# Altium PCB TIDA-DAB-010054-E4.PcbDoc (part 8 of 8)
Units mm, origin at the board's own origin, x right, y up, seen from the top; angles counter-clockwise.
Board outline 300 x 180 mm, 4 copper layers (Top Layer, Inner Layer1, Inner Layer2, Bottom Layer), stack 1.605 mm thick; 873 components, 388 nets, 2405 pads, 1542 vias.
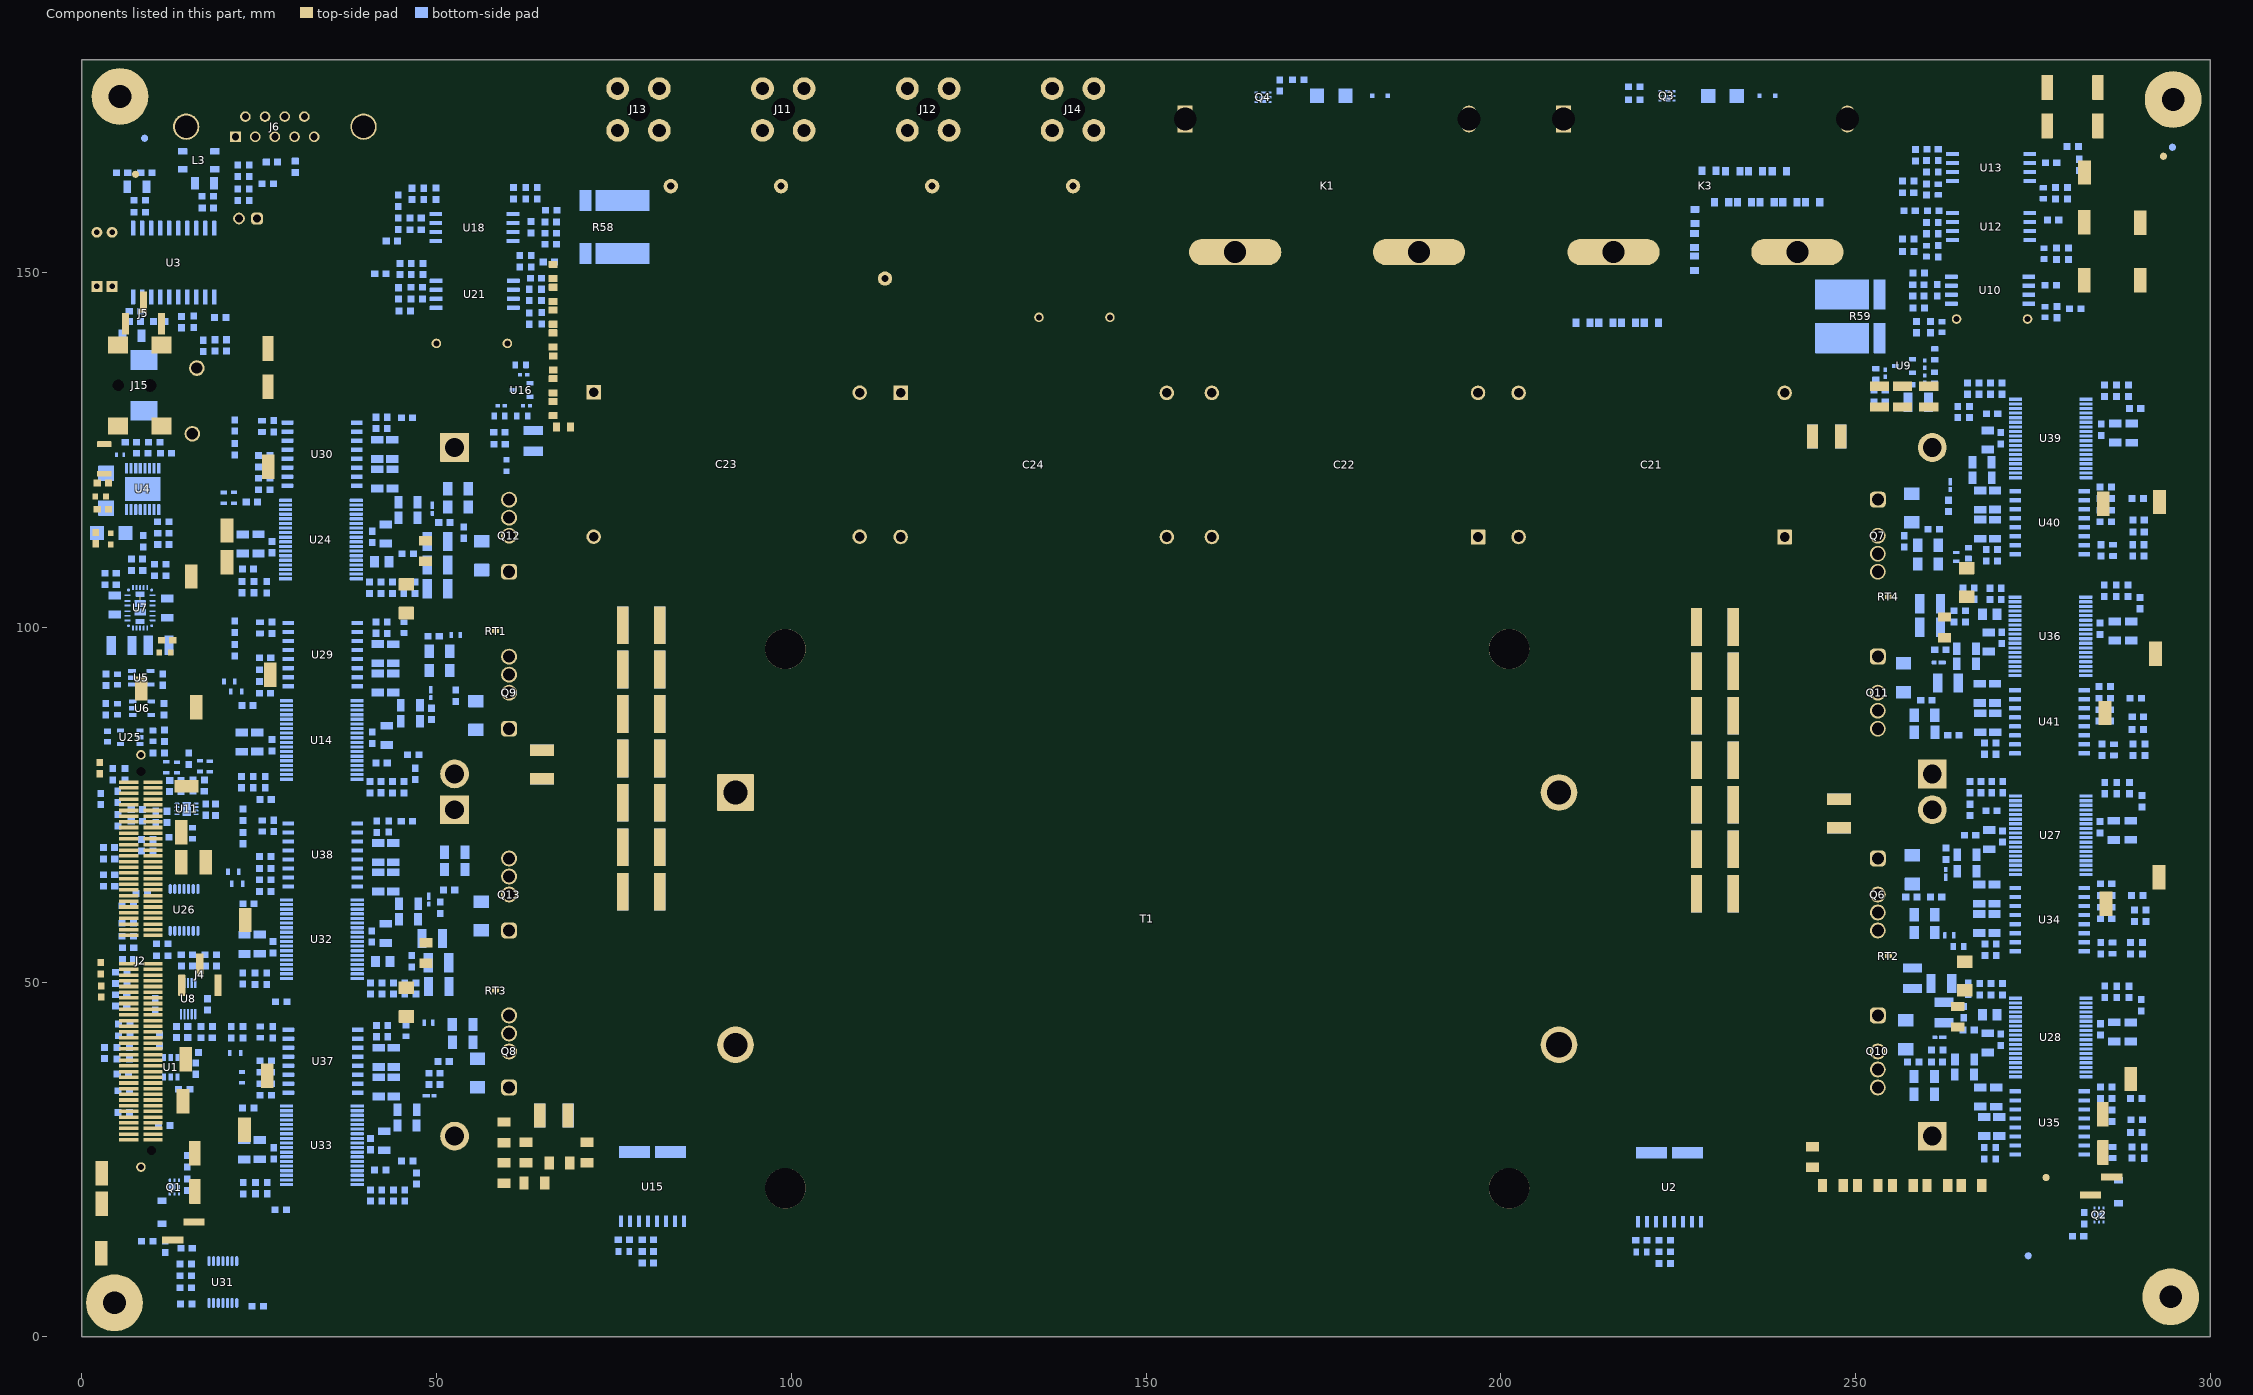
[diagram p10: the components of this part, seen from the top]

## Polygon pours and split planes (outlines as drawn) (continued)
-4V_BOT2 on Bottom Layer "BOTTOM_LAYER_-4V_BOT2_P194" (solid, remove dead copper, pour order 194): 42.729,54.117 42.61,53.998 40.244,53.998 39.815,53.569 37.904,53.569 37.904,54.664 42.729,54.664
+15V_BOT2 on Bottom Layer "BOTTOM_LAYER_+15V_BOT2_P193" (solid, remove dead copper, pour order 193): 37.92,55.769 37.904,55.753 37.904,54.857 46.897,54.857 46.897,57.232 44.868,57.232 43.563,55.927 39.89,55.927 39.745,55.782
-4V_BOT2 on Bottom Layer "BOTTOM_LAYER_-4V_BOT2_P192" (solid, remove dead copper, pour order 192): 39.852,63.799 40.108,63.543 45.372,63.543 45.372,57.916 44.478,57.916 42.956,56.394 39.945,56.394 39.549,55.999 39.534,56.014 37.924,56.014 37.924,63.799
S2L_P on Bottom Layer "BOTTOM_LAYER_S2L_P_P191" (solid, remove dead copper, pour order 191): 46.168,71.806 47.109,71.806 47.109,69.047 37.938,69.047 37.938,69.982 37.924,69.997 37.924,70.257 39.549,70.257 41.098,71.806
+15V_BOT2 on Bottom Layer "BOTTOM_LAYER_+15V_BOT2_P190" (solid, remove dead copper, pour order 190): 37.924,67.629 37.924,66.968 37.953,66.938 39.815,66.938 40.525,66.228 40.525,65.532 41.118,64.94 47.009,64.94 47.009,67.629 39.94,67.629 39.549,67.629
-4V_TOP1 on Bottom Layer "BOTTOM_LAYER_-4V_TOP1_P006" (solid, remove dead copper, pour order 6): 39.81,92.033 40.315,91.528 45.472,91.528 45.472,86.15 44.578,86.15 43.056,84.628 40.045,84.628 39.649,84.233 39.634,84.248 38.024,84.248 38.024,91.88 38.039,92.023 38.05,92.033
+15V_TOP1 on Bottom Layer "BOTTOM_LAYER_+15V_TOP1_P007" (solid, remove dead copper, pour order 7): 38.02,84.003 38.004,83.987 38.004,82.898 46.997,82.898 46.997,85.466 44.968,85.466 43.663,84.161 39.99,84.161 39.845,84.016
-4V_TOP1 on Bottom Layer "BOTTOM_LAYER_-4V_TOP1_P008" (solid, remove dead copper, pour order 8): 38.004,81.618 42.829,81.618 42.829,82.698 38.033,82.698 38.004,82.669
S1H_P on Bottom Layer "BOTTOM_LAYER_S1H_P_P175" (solid, remove dead copper, pour order 175): 44.998,79.015 44.217,79.015 42.958,80.274 42.564,80.274 42.564,81.34 44.998,81.34
S1L_P on Bottom Layer "BOTTOM_LAYER_S1L_P_P182" (solid, remove dead copper, pour order 182): 37.92,125.832 47.596,125.832 47.596,128.515 41.319,128.515 39.549,126.745 37.92,126.745
+15V_TOP1 on Bottom Layer "BOTTOM_LAYER_+15V_TOP1_P004" (solid, remove dead copper, pour order 4): 38.024,95.862 38.024,95.202 38.053,95.172 39.915,95.172 40.625,94.462 40.625,92.89 47.109,92.89 47.109,95.862 40.04,95.862 39.649,95.862
S1H_P on Bottom Layer "BOTTOM_LAYER_S1H_P_P005" (solid, remove dead copper, pour order 5): 40.416,97.507 40.869,97.054 40.869,97.048 47.352,97.048 47.352,97.509 47.35,97.511 47.35,98.461 46.03,99.78 40.939,99.78 39.649,98.491 38.024,98.491 38.024,98.23 38.038,98.216 38.038,97.507
-4V_TOP1 on Bottom Layer "BOTTOM_LAYER_-4V_TOP1_P176" (solid, remove dead copper, pour order 176): 46.356,77.031 40.143,77.031 39.709,77.465 39.709,79.433 38.053,79.433 38.03,79.411 38.059,79.382 38.059,76.224 46.356,76.224
+15V_BOT1 on Bottom Layer "BOTTOM_LAYER_+15V_BOT1_P181" (solid, remove dead copper, pour order 181): 37.923,124.117 37.923,123.456 37.953,123.427 39.815,123.427 40.525,122.716 40.525,121.678 46.773,121.678 46.773,124.296 40.119,124.296 39.94,124.117 39.549,124.117
-4V_BOT1 on Bottom Layer "BOTTOM_LAYER_-4V_BOT1_P183" (solid, remove dead copper, pour order 183): 37.939,120.277 37.949,120.287 40.288,120.287 45.372,120.287 45.372,114.404 44.478,114.404 42.956,112.882 39.944,112.882 39.549,112.487 39.534,112.502 37.923,112.502 37.923,120.135
+15V_BOT1 on Bottom Layer "BOTTOM_LAYER_+15V_BOT1_P184" (solid, remove dead copper, pour order 184): 37.92,112.257 37.904,112.241 37.904,111.152 46.897,111.152 46.897,113.72 44.867,113.72 43.562,112.415 39.889,112.415 39.744,112.27
-4V_BOT1 on Bottom Layer "BOTTOM_LAYER_-4V_BOT1_P185" (solid, remove dead copper, pour order 185): 43.149,110.256 40.052,110.256 39.649,109.854 39.631,109.872 37.904,109.872 37.904,110.923 37.932,110.952 43.149,110.952
-4V_BOT1 on Bottom Layer "BOTTOM_LAYER_-4V_BOT1_P186" (solid, remove dead copper, pour order 186): 46.255,105.285 40.043,105.285 39.608,105.719 39.608,107.688 37.952,107.688 37.93,107.665 37.958,107.636 37.958,104.207 46.255,104.207
I_SEC_P on Bottom Layer "BOTTOM_LAYER_I_SEC_P_P168" (solid, remove dead copper, pour order 168): 218.51,24.8 218.51,29.163 218.497,29.163 215.02,32.64 203.84,32.64 202.76,33.72 202.76,48.58 203.24,49.06 215.761,49.06 223.48,41.341 223.48,24.86 223.54,24.8
D1L_S on Bottom Layer "Bottom Layer-D1L_S" (solid, remove dead copper, pour order 166): 23 vertices, not listed, extent 223.927,24.88 254.4,63.494
D1H_S on Bottom Layer "BOTTOM_LAYER_D1H_S_P158" (solid, remove dead copper, pour order 158): 254.665,66.525 254.665,69.805 252.504,71.966 245.259,71.966 245.259,66.525
SGND on Bottom Layer "BOTTOM_LAYER_SGND_P148" (solid, remove dead copper, pour order 148): 254.64,39.014 254.64,40.415 253.727,41.328 245.628,41.328 245.101,40.801 245.101,35.554 245.041,35.494 250.12,35.494 250.12,39.014
D1H_P on Bottom Layer "BOTTOM_LAYER_D1H_P_P141" (solid, remove dead copper, pour order 141): 58.004,82.647 58.147,82.504 66.589,82.504 66.589,86.005 65.955,86.639 58.372,86.639 58.004,86.271
D1L_P on Bottom Layer "BOTTOM_LAYER_D1L_P_P126" (solid, remove dead copper, pour order 126): 19 vertices, not listed, extent 57.526,60.16 77.16,108.759
PGND on Bottom Layer "BOTTOM_LAYER_PGND_P050" (solid, remove dead copper, pour order 50): 67.916,65.34 63.63,65.34 63.63,63.574 57.976,63.6 57.976,61.192 67.916,61.192
D2L_P on Bottom Layer "BOTTOM_LAYER_D2L_P_P054" (solid, remove dead copper, pour order 54): 20 vertices, not listed, extent 57.712,24.735 80.389,58.185
I_PRI_P on Bottom Layer "BOTTOM_LAYER_I_PRI_P_P066" (solid, remove dead copper, pour order 66): 80.72,24.72 80.72,41.66 84.186,45.126 95.029,45.126 96.56,43.595 96.56,37.42 93.22,34.08 86.82,34.08 85.645,32.905 85.645,24.72
D1H_P on Bottom Layer "BOTTOM_LAYER_D1H_P_P110" (solid, remove dead copper, pour order 110): 57.776,35.251 57.776,29.727 64.954,29.727 64.954,36.049 58.575,36.049
VBATT_P on Bottom Layer "BOTTOM_LAYER_VBATT_P_P095" (solid, remove dead copper, pour order 95): 147.76,147.76 121.75,147.76 113.531,155.911 113.531,177.491 126.031,177.491 126.031,161.911 133.291,154.651 169.751,154.651 169.751,147.76
VBUS_N on Bottom Layer "BOTTOM_LAYER_VBUS_N_P076" (solid, remove dead copper, pour order 76): 72.371,158.642 72.371,178.38 85.6,178.38 85.6,162.86 81.382,158.642
SGND on Top Layer "TOP_LAYER_SGND_P385" (solid, remove dead copper, pour order 385): 248.479,30.15 252.365,26.264 262.763,26.264 262.763,30.251 262.712,30.302 252.031,30.302 250.12,32.213 250.139,32.233 246.837,32.233 246.837,30.15
PGND on Top Layer "TOP_LAYER_PGND_P381" (solid, remove dead copper, pour order 381): 50.576,127.332 50.597,127.312 50.597,123.292 62.001,123.292 64.541,120.752 67.64,120.752 67.64,122.33 62.585,127.385
GND on Top Layer "TOP_LAYER_GND_P379" (solid, remove dead copper, pour order 379): 15.189,27.635 15.215,27.661 16.739,27.661 16.739,24.257 15.113,22.631 11.557,22.631 11.557,23.647 15.189,27.28 15.189,27.61
VBATT_P on Top Layer "TOP_LAYER_VBATT_P_P087" (solid, remove dead copper, pour order 87): 121.9,147.58 169.98,147.58 169.98,154.734 133.466,154.734 126.26,161.94 126.26,177.44 113.76,177.44 113.76,155.72
D1H_P on Top Layer "TOP_LAYER_D1H_P_P072" (solid, remove dead copper, pour order 72): 92.12,177.599 92.12,138.3 90.415,136.595 75.521,136.595 70.14,131.214 70.14,106.369 154.62,106.369 154.62,136.98 108.14,136.98 105.72,139.4 105.72,177.582
GND on Top Layer "TOP_LAYER_GND_P294" (solid, remove dead copper, pour order 294): 23.706,61.992 27.91,61.992 27.91,55.332 23.706,55.332
-4V_BOT2 on Top Layer "TOP_LAYER_-4V_BOT2_P271" (solid, remove dead copper, pour order 271): 37.95,63.799 37.973,63.776 40.991,63.776 43.719,61.048 43.719,57.916 43.719,53.776 41.467,51.524 41.467,47.679 37.874,47.679
GND on Top Layer "TOP_LAYER_GND_P282" (solid, remove dead copper, pour order 282): 23.566,118.312 27.679,118.312 27.679,111.652 23.566,111.652
12V on Top Layer "TOP_LAYER_12V_P373" (solid, pour order 373): 73 vertices, not listed, extent 10.646,9.912 291.897,135.734
RTN on Top Layer "TOP_LAYER_RTN_P304" (solid, remove dead copper, pour order 304): 6.082,126.557 14.116,126.557 14.116,110.922 6.082,110.922
GND on Top Layer "TOP_LAYER_GND_P377" (solid, remove dead copper, pour order 377): 273.66,172.48 273.66,168.98 284.74,168.98 284.96,169.2 284.96,172.48
GND on Top Layer "TOP_LAYER_GND_P376" (solid, remove dead copper, pour order 376): 25.475,137.528 25.533,137.586 27.042,137.586 27.042,143.181 24.763,143.181 24.763,141.65 25.417,140.996
12V on Top Layer "TOP_LAYER_12V_P375" (solid, remove dead copper, pour order 375): 18 vertices, not listed, extent 193.44,169.74 284.96,177.7
+15V_TOP4 on Top Layer "TOP_LAYER_+15V_TOP4_P230" (solid, remove dead copper, pour order 230): 267.066,114.977 267.066,127.981 264.915,127.981 264.915,114.977
+15V_BOT3 on Top Layer "TOP_LAYER_+15V_BOT3_P257" (solid, remove dead copper, pour order 257): 267.066,30.708 267.066,43.397 264.371,43.397 264.371,33.402
+15V_TOP3 on Top Layer "TOP_LAYER_+15V_TOP3_P248" (solid, remove dead copper, pour order 248): 267.066,58.414 267.066,72.044 264.371,72.044 264.371,58.414
+15V_BOT4 on Top Layer "TOP_LAYER_+15V_BOT4_P239" (solid, remove dead copper, pour order 239): 267.066,86.619 267.066,100.249 264.371,100.249 264.371,86.619
GND_SEN_SEC on Top Layer "TOP_LAYER_GND_SEN_SEC_P369" (solid, remove dead copper, pour order 369): 252.016,133.396 254.716,133.396 254.716,138.243 252.016,138.243
VBUS_N on Top Layer "TOP_LAYER_VBUS_N_P074" (solid, remove dead copper, pour order 74): 72.371,158.689 72.371,178.38 85.6,178.38 85.6,162.88 81.409,158.689
+15V_TOP2 on Top Layer "TOP_LAYER_+15V_TOP2_P212" (solid, remove dead copper, pour order 212): 44.314,39.255 44.314,25.624 47.009,25.624 47.009,39.255
+15V_BOT1 on Top Layer "TOP_LAYER_+15V_BOT1_P187" (solid, remove dead copper, pour order 187): 44.314,124.783 44.314,111.152 47.009,111.152 47.009,124.783
+15V_TOP1 on Top Layer "TOP_LAYER_+15V_TOP1_P010" (solid, remove dead copper, pour order 10): 44.414,96.528 44.414,82.898 47.109,82.898 47.109,96.528
+15V_BOT2 on Top Layer "TOP_LAYER_+15V_BOT2_P195" (solid, remove dead copper, pour order 195): 44.314,68.295 44.314,54.664 47.009,54.664 47.009,68.295
GND on Top Layer "TOP_LAYER_GND_P350" (solid, remove dead copper, pour order 350): 289.89,120.703 283.666,120.703 283.666,127.363 289.89,127.363
GND on Top Layer "TOP_LAYER_GND_P346" (solid, remove dead copper, pour order 346): 288.874,92.643 283.641,92.643 283.641,99.303 288.874,99.303
GND on Top Layer "TOP_LAYER_GND_P342" (solid, remove dead copper, pour order 342): 289.267,64.766 283.592,64.766 283.592,71.427 289.267,71.427
GND on Top Layer "TOP_LAYER_GND_P334" (solid, remove dead copper, pour order 334): 287.674,39.218 287.902,39.446 288.595,39.446 288.595,42.903 283.553,42.903 283.553,36.243 284.132,35.664 284.132,29.662 285.578,29.662 285.61,29.629 285.613,29.633 285.613,34.263 287.63,36.243 287.674,36.243
NetC31_1 on Top Layer "TOP_LAYER_NETC31_1_P326" (solid, remove dead copper, pour order 326): 17 vertices, not listed, extent 80.68,60.09 97.02,103.02
AGND on Top Layer "TOP_LAYER_AGND_P311" (solid, pour order 311): 7.67,105.03 7.665,104.29 8.836,104.29 8.836,105.03
GND on Top Layer "TOP_LAYER_GND_P312" (solid, remove dead copper, pour order 312): 7.408,103.83 9.067,103.83 9.067,101.66 7.408,101.66
GND on Top Layer "TOP_LAYER_GND_P298" (solid, remove dead copper, pour order 298): 23.706,32.952 27.765,32.952 27.765,26.292 23.706,26.292
GND on Top Layer "TOP_LAYER_GND_P286" (solid, remove dead copper, pour order 286): 23.667,90.058 27.732,90.058 27.732,83.398 23.667,83.398
VBATT_N on Top Layer "TOP_LAYER_VBATT_N_P279" (solid, remove dead copper, pour order 279): 18 vertices, not listed, extent 133.16,149.08 223.44,177.44
-4V_TOP4 on Top Layer "TOP_LAYER_-4V_TOP4_P277" (solid, remove dead copper, pour order 277): 273.43,118.121 273.407,118.144 267.661,118.144 267.661,124.004 267.661,129.879 269.061,129.879 269.913,130.731 269.913,134.384 273.363,134.384 273.506,134.241
-4V_BOT3 on Top Layer "TOP_LAYER_-4V_BOT3_P276" (solid, remove dead copper, pour order 276): 273.43,33.537 273.407,33.561 267.683,33.561 267.661,33.583 267.661,39.42 267.661,45.295 269.061,45.295 269.913,46.147 269.913,49.8 273.363,49.8 273.506,49.657
-4V_TOP3 on Top Layer "TOP_LAYER_-4V_TOP3_P275" (solid, remove dead copper, pour order 275): 273.43,62.184 273.407,62.208 267.661,62.208 267.661,68.067 267.661,73.943 269.061,73.943 269.913,74.795 269.913,78.448 273.363,78.448 273.506,78.305
-4V_BOT4 on Top Layer "TOP_LAYER_-4V_BOT4_P274" (solid, remove dead copper, pour order 274): 273.406,90.677 273.382,90.701 267.636,90.701 267.636,96.56 267.636,102.436 269.036,102.436 269.888,103.288 269.888,106.39 273.479,106.39
-4V_TOP2 on Top Layer "TOP_LAYER_-4V_TOP2_P272" (solid, pour order 272): 37.95,34.759 37.973,34.736 43.719,34.736 43.719,28.876 43.719,25.22 41.467,22.968 41.467,19.155 37.877,19.155
-4V_TOP1 on Top Layer "TOP_LAYER_-4V_TOP1_P270" (solid, remove dead copper, pour order 270): 38.05,92.033 38.073,92.009 43.819,92.009 43.819,86.15 43.819,82.99 41.567,80.738 41.567,76.019 37.975,76.019
-4V_BOT1 on Top Layer "TOP_LAYER_-4V_BOT1_P269" (solid, remove dead copper, pour order 269): 37.949,120.287 37.973,120.264 46.997,120.264 46.997,114.522 46.879,114.404 43.719,114.404 43.719,108.529 42.319,108.529 41.467,107.677 41.467,104.289 37.874,104.289
NetC32_2 on Top Layer "TOP_LAYER_NETC32_2_P268" (solid, remove dead copper, pour order 268): 205.34,70.08 217.38,70.08 219.44,68.02 219.44,61.7 221.48,59.66 228.34,59.66 228.3,102.66 221.4,102.66 219.44,100.7 219.44,87.06 216.991,84.611 205.63,84.611 203.9,82.881 203.9,71.52
D1L_P on Top Layer "TOP_LAYER_D1L_P_P043" (solid, remove dead copper, pour order 43): 18 vertices, not listed, extent 57.526,60.16 77.16,108.793
SGND on Top Layer "TOP_LAYER_SGND_P223" (solid, remove dead copper, pour order 223): 262.788,75.041 262.788,81.4 245.569,81.4 245.569,75.041
SGND on Top Layer "TOP_LAYER_SGND_P219" (solid, remove dead copper, pour order 219): 244.143,125.163 239.011,125.163 239.011,130.891 238.939,130.962 238.989,131.012 244.143,131.012
PGND on Top Layer "TOP_LAYER_PGND_P203" (solid, remove dead copper, pour order 203): 68.44,28.62 68.44,33.127 72.417,33.127 72.417,26.608 70.452,26.608
PGND on Top Layer "TOP_LAYER_PGND_P199" (solid, remove dead copper, pour order 199): 51.968,79.503 51.968,72.288 67.916,72.288 67.916,79.503
NetK3_4 on Top Layer "TOP_LAYER_NETK3_4_P103" (solid, remove dead copper, pour order 103): 233.88,144.737 233.88,155.229 233.86,155.249 251.884,155.104 251.884,144.737
I_SEC_P on Top Layer "TOP_LAYER_I_SEC_P_P169" (solid, remove dead copper, pour order 169): 218.51,24.8 218.51,29.163 218.497,29.163 215.02,32.64 203.84,32.64 202.76,33.72 202.76,48.58 203.24,49.06 215.78,49.06 223.48,41.36 223.48,24.86 223.54,24.8
D1L_S on Top Layer "Top Layer-D1L_S" (solid, remove dead copper, pour order 164): 18 vertices, not listed, extent 223.927,24.88 254.63,63.494
SGND on Top Layer "TOP_LAYER_SGND_P159" (solid, remove dead copper, pour order 159): 245.259,84.081 245.259,90.354 246.837,91.932 255.394,91.932 255.394,89.654 255.3,89.56 250.639,89.56 250.639,84.493 250.22,84.074
D1H_S on Top Layer "TOP_LAYER_D1H_S_P156" (solid, remove dead copper, pour order 156): 254.665,66.525 254.665,69.733 252.379,72.018 245.259,72.018 245.259,66.525
SGND on Top Layer "TOP_LAYER_SGND_P146" (solid, remove dead copper, pour order 146): 254.64,39.014 254.64,41.352 245.652,41.352 245.101,40.801 245.101,35.554 245.041,35.494 250.12,35.494 250.12,39.014
D1H_P on Top Layer "TOP_LAYER_D1H_P_P136" (solid, remove dead copper, pour order 136): 58.004,82.647 58.147,82.504 66.589,82.504 66.589,86.005 65.955,86.639 58.372,86.639 58.004,86.271
PGND on Top Layer "TOP_LAYER_PGND_P037" (solid, remove dead copper, pour order 37): 58.004,114.084 58.004,111.782 67.08,111.782 67.08,116.44 63.762,116.44 63.18,115.858 61.382,114.068
PGND on Top Layer "TOP_LAYER_PGND_P051" (solid, remove dead copper, pour order 51): 67.916,65.34 63.63,65.34 63.63,63.574 57.976,63.6 57.976,61.192 63.363,61.234 67.916,61.199
D2L_P on Top Layer "TOP_LAYER_D2L_P_P064" (solid, remove dead copper, pour order 64): 19 vertices, not listed, extent 57.676,24.72 80.354,58.199
I_PRI_P on Top Layer "TOP_LAYER_I_PRI_P_P065" (solid, remove dead copper, pour order 65): 80.74,24.72 80.74,41.68 84.186,45.126 94.914,45.126 96.56,43.48 96.56,37.42 93.24,34.1 86.84,34.1 85.75,33.01 85.75,24.72
D1H_P on Top Layer "TOP_LAYER_D1H_P_P108" (solid, remove dead copper, pour order 108): 57.776,36.049 57.776,29.727 64.954,29.727 64.954,36.049
D2L_S on Top Layer "TOP_LAYER_D2L_S_P121" (solid, remove dead copper, pour order 121): 19 vertices, not listed, extent 232.06,59.8 255.394,113.989
D1H_S on Top Layer "Top Layer-D1H_S" (solid, remove dead copper, pour order 117): 28 vertices, not listed, extent 157.6,106.37 255.062,154.68

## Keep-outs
Keep-Out Layer:
  lines w0.254: 194.784,13.944 194.784,103.944 194.775,103.936 104.254,103.936 104.245,103.927 104.245,13.944 194.784,13.944 ; 194.784,13.944 194.784,13.944

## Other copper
Top Layer:
  text ".Layer_Name" at 14.656,-21.806 h1.52
Inner Layer1:
  text ".Layer_Name" at 14.656,-21.806 h1.52
Inner Layer2:
  text ".Layer_Name" at 14.656,-21.806 h1.52
Bottom Layer:
  text ".Layer_Name" at 14.656,-21.806 h1.52

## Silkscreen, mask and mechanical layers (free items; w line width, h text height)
Top Overlay:
  lines w0.15: 68.44,33.607 68.44,76.28
  lines w0.5: 8.346,16.022 10.427,16.022 ; 9.386,14.981 9.386,17.062 ; 18.217,16.199 20.298,16.199 ; 75.548,157.54 79.788,157.54 ; 96.54,157.54 100.78,157.54 ; 98.66,155.42 98.66,159.66 ; 118.02,157.8 122.26,157.8 ; 120.14,155.649 120.14,159.889 ; 137.6,157.8 141.84,157.8 ; 278.486,21.641 280.568,21.641 ; 279.527,20.6 279.527,22.681 ; 288.876,22.022 290.957,22.022
  text "VBUS_P" at 96.223,166.281 h0.89
  text "VBUS_N" at 75.932,166.161 h0.89
  text "VBATT_N" at 135.922,166.12 h0.89
  text "VBATT_P" at 116.636,165.96 h0.89
  text "DOUT_V_BATT" at 271.17,163.369 h0.89
  text "GND" at 291.871,156.489 h0.89
  text "DOUT_VDC_SEC" at 270.027,155.876 h0.89
  text "MAX: 500V, 20A" at 122.601,153.005 h2
  text "MAX: 800V, 12.5A" at 77.262,152.344 h2
  text "DOUT_I_DC_SEC" at 269.392,148.891 h0.89
  text "CLK" at 291.871,148.742 h0.89
  text "Danger High Voltage" at 96.718,143.08 h2
  text "12V 2.5A" at 19.934,129.027 h2
  text "DESAT_SEC" at 294.687,119.736 h0.89 r270
  text "DESAT_PRI" at 17.827,119.355 h0.89 r270
  text "RST" at 17.805,110.211 h0.89 r270
  text "12V" at 14.503,104.623 h0.89 r270
  text "GND" at 294.03,97.384 h0.89 r270
  text "I_MON" at 5.889,93.32 h0.89 r270
  text "GND" at 13.614,90.399 h0.89 r270
  text "I_DC_PRI" at 17.404,77.277 h0.89
  text "V_DC_PRI" at 15.773,71.548 h0.89
  text "I_TANK_SEC" at 19.456,67.992 h0.89
  text "GND" at 294.665,65.888 h0.89 r270
  text "I_TANK_PRI" at 12.725,63.547 h0.89
  text "RST_MCU" at 16.281,39.798 h0.89
  text "CLK_DELAYED" at 16.251,32.566 h0.89
  text "GND" at 20.472,30.201 h0.89 r270
  text "GND" at 0.523,24.395 h0.6 r270
  text "FLT_SEC" at 4.343,17.7 h0.89
  text "12V FAN" at 283.845,16.713 h0.89
  text "FLT_PRI" at 4.343,11.35 h0.89
  text "12V FAN" at 10.439,10.312 h0.89
  text ".PRJ_Number" at 130.84,5.94 h5
  text ".PCB_Rev" at 168.46,5.96 h5
  text ".Layer_Name" at 14.375,-21.925 h1.52
Bottom Overlay:
  circle w0.254: c272.136,109.017 r0.114
  circle w0.254: c271.526,81.026 r0.114
  circle w0.254: c271.221,53.188 r0.114
  circle w0.254: c272.11,24.282 r0.114
  circle w0.254: c39.065,44.729 r0.114
  circle w0.254: c39.065,73.711 r0.114
  circle w0.254: c39.218,101.905 r0.114
  circle w0.254: c39.141,130.429 r0.114
  lines w0.254: 264.82,47.32 264.82,51.334
  text "Danger High Voltage" at 111.663,142.648 h2
  text ".Layer_Name" at 14.656,-21.806 h1.52
Top Paste:
  text ".Layer_Name" at 14.656,-21.806 h1.52
Bottom Paste:
  text ".Layer_Name" at 14.656,-21.806 h1.52
Top Solder:
  text ".Layer_Name" at 14.656,-21.806 h1.52
Bottom Solder:
  text ".Layer_Name" at 14.656,-21.806 h1.52
M1 Board Outline:
  lines w0.254: 0,0 0,180 300,180 300,0 0,0 ; 104.245,13.944 104.245,103.944 194.784,103.944 194.784,13.944 104.245,13.944
  text ".Layer_Name" at 14.656,-21.806 h1.52
M2 Board Dimensions:
  rectangle: 3.175,-10.16 12.7,-6.985
  rectangle: 0,-6.985 3.175,-3.81
  lines w0.178: 0,-6.985 25.4,-6.985 ; 3.175,-10.16 3.175,-3.81 ; 6.35,-10.16 6.35,-3.81 ; 12.7,-10.16 12.7,-3.81 ; 19.05,-10.16 19.05,-3.81 ; 0,-10.16 0,-3.81 25.4,-3.81 25.4,-10.16 0,-10.16
  text ".Layer_Name" at 14.656,-21.806 h1.52
M3 3D STEP Top:
  text ".Layer_Name" at 14.656,-21.806 h1.52
M4 3D STEP Bottom:
  text ".Layer_Name" at 14.656,-21.806 h1.52
M5 Assembly Top:
  circle w0.254: c415.758,-35.499 r0.205
  lines w0.254: -7.417,-23.626 160.223,-23.626 ; -7.417,-18.462 160.274,-18.462 ; -7.417,-13.297 -7.417,-28.791 94.31,-28.791 160.274,-28.791 160.274,-13.297 -7.404,-13.297 -7.404,-28.791 32.614,-28.791 ; 55.194,-28.791 55.194,-13.297 ; 87.376,-18.462 87.376,-13.297 ; 108.712,-18.462 108.712,-13.297 ; 124.511,-28.956 124.511,-23.804
  text "COMPONENTS MARKED 'DNP' SHOULD NOT BE POPULATED." at 29.299,-8.09 h1.52
  text "ASSEMBLY VARIANT:" at 29.286,-11.024 h1.52
  text ".VariantName" at 55.601,-11.024 h1.52
  text "PCB VIEWED FROM TOP SIDE" at -5.804,-16.654 h1.52
  text "BOARD #:" at 57.099,-16.654 h1.52
  text ".PRJ_Number" at 70.955,-16.654 h1.52
  text "REV:" at 92.405,-16.654 h1.52
  text ".PCB_Rev" at 99.809,-16.654 h1.52
  text "SVN REV:" at 113.69,-16.654 h1.52
  text ".VersionControl_RevNumber" at 126.543,-16.654 h1.52
  text "PLOT NAME =" at -5.804,-27.034 h1.52
  text ".plot_File_Name" at 14.656,-27.034 h1.52
  text "GENERATED    :" at 57.15,-27.034 h1.52
  text ".Print_Date" at 79.235,-27.034 h1.52
  text ".Print_Time" at 97.752,-27.034 h1.52
  text "TEXAS INSTRUMENTS" at 129.87,-27.034 h1.52
M6 Assembly Bottom:
  lines w0.254: -7.429,-18.474 160.261,-18.474 ; -7.379,-23.639 160.261,-23.639 ; 28.334,-28.969 28.334,-23.817 ; 44.133,-18.474 44.133,-13.31 ; 65.468,-18.474 65.468,-13.31 ; 97.65,-28.804 97.65,-13.31 ; 120.231,-28.804 160.249,-28.804 160.249,-13.31 -7.429,-13.31 -7.429,-28.804 58.534,-28.804 160.261,-28.804 160.261,-13.31
  text "COMPONENTS MARKED 'DNP' SHOULD NOT BE POPULATED." at 154.991,-8.077 h1.52
  text ".VariantName" at 128.473,-11.024 h1.52
  text "ASSEMBLY VARIANT:" at 154.864,-11.024 h1.52
  text ".VersionControl_RevNumber" at 26.302,-16.667 h1.52
  text "SVN REV:" at 39.154,-16.667 h1.52
  text ".PCB_Rev" at 53.035,-16.667 h1.52
  text "REV:" at 60.439,-16.667 h1.52
  text ".PRJ_Number" at 81.89,-16.667 h1.52
  text "BOARD #:" at 95.745,-16.667 h1.52
  text "PCB VIEWED FROM BOTTOM SIDE" at 158.648,-16.667 h1.52
  text "TEXAS INSTRUMENTS" at 22.974,-27.047 h1.52
  text ".Print_Time" at 55.093,-27.047 h1.52
  text ".Print_Date" at 73.609,-27.047 h1.52
  text "GENERATED    :" at 95.694,-27.047 h1.52
  text ".plot_File_Name" at 138.189,-27.047 h1.52
  text "PLOT NAME =" at 158.648,-27.047 h1.52
M9 Title Sheet:
  drawing of 56 lines, arcs and shapes, not listed
  text "1" at 26.882,339.887 h1.78
  text "2" at 111.354,339.887 h1.78
  text "3" at 195.936,339.887 h1.78
  text "4" at 280.645,339.887 h1.78
  text "5" at 365.1,339.887 h1.78
  text "6" at 449.809,339.887 h1.78
  text "A" at -11.76,294.726 h1.78
  text "A" at 488.62,294.726 h1.78
  text "B" at -11.76,199.476 h1.78
  text "B" at 488.62,199.476 h1.78
  text "C" at -11.76,104.226 h1.78
  text "C" at 488.62,104.226 h1.78
  text "D" at -11.76,8.976 h1.78
  text "D" at 488.62,8.976 h1.78
  text "PROJECT TITLE:" at 410.032,6.817 h1.14
  text ".PRJ_Title" at 411.302,3.431 h1.78
  text "DESIGNED FOR:" at 410.032,-0.828 h1.14
  text ".PRJ_Customer" at 411.302,-4.384 h1.78
  text "FILE NAME:" at 410.032,-8.448 h1.14
  text ".PCB_File_Name_No_Path" at 411.302,-11.496 h1.78
  text "Texas Instruments (TI) and/or its licensors do not warrant the accuracy or completeness of this specification" at 283.807,-15.607 h1.14
  text "ENGINEER:" at 410.032,-15.814 h1.14
  text "LAYOUT BY:" at 448.259,-15.814 h1.14
  text "or any information contained therein. TI and/or its licensors do not warrant that this design will meet" at 282.664,-18.469 h1.14
  text ".PRJ_Engineer" at 411.302,-19.751 h1.78
  text ".PCB_Layout" at 449.542,-19.751 h1.78
  text "the specifications, will be suitable for your application or fit for any particular purpose, or will operate in" at 282.664,-21.33 h1.14
  text ".Layer_Name" at 14.656,-21.806 h1.52
  text "ALTIUM DESIGNER VERSION:" at 448.259,-23.688 h1.14
  text "an implementation. TI and/or its licensors do not warrant that the design is production worthy. You should" at 282.664,-24.192 h1.14
  text "completely validate and test your design implementation to confirm the system functionality for your application." at 283.807,-27.054 h1.14
  text ".print_Scale" at 411.302,-27.075 h1.78
  text ".Application_BuildNumber" at 449.542,-27.075 h1.78
  text "1" at 26.882,-33.493 h1.78
  text "2" at 111.354,-33.493 h1.78
  text "3" at 195.936,-33.493 h1.78
  text "4" at 280.645,-33.493 h1.78
  text "5" at 365.1,-33.493 h1.78
  text "6" at 449.809,-33.493 h1.78
M10 Fab Notes:
  drawing of 228 lines, arcs and shapes, not listed
  text "DETAIL-A : BOARD CUTOUT SHOULD BE PROVIDED FOR THE GIVEN AREA." at 407.013,176.884 h1.52
  text "DESIGN INFORMATION" at 436.423,172.616 h1.52
  text "(REFER ALSO ARRAY/PANEL PROFILING INFORMATION)" at 427.24,168.508 h1.52
  text "BOARD SIZE" at 409.815,168.399 h1.52
  text "300MM" at 421.558,165.153 h1.52
  text "X" at 434.402,165.153 h1.52
  text "180MM" at 440.278,165.153 h1.52
  text "Number of Layers :" at 420.051,160.144 h1.52
  text "4" at 447.86,159.89 h1.52
  text "MIN. TRACK WIDTH:" at 420.051,156.614 h1.52
  text "MIL" at 451.827,156.614 h1.52
  text "8" at 447.933,156.539 h1.52
  text "MIL" at 451.843,153.641 h1.52
  text "7.87" at 445.863,153.438 h1.52
  text "MIN. CLEARANCE:" at 420.051,153.261 h1.52
  text "7.874" at 443.958,150.237 h1.52
  text "MIL" at 451.919,150.237 h1.52
  text "MIN. VIA DRILL SIZE:" at 420.051,149.908 h1.52
  text "MINIMUM ANNULAR RING" at 411.689,146.2 h1.52
  text "EXTERNAL" at 455.688,146.2 h1.52
  text "5.90 MIL" at 438.203,146.148 h1.52
  text "PER" at 416.769,143.202 h1.52
  text "IPC-D-275 CLASS 2 LEVEL C" at 422.357,143.202 h1.52
  text "+/-" at 450.19,140.332 h1.52
  text "MIL, HOLES" at 460.158,140.35 h1.52
  text "+/-" at 471.881,140.332 h1.52
  text "REGISTRATION TOLERANCES:" at 411.689,140.205 h1.52
  text "METAL" at 442.163,140.205 h1.52
  text "5" at 456.799,140.205 h1.52
  text "3" at 477.957,140.205 h1.52
  text "MIL" at 480.91,140.205 h1.52
  text "MATERIAL:" at 409.79,134.885 h1.52
  text "FR-4 High Tg" at 434.846,131.32 h1.52
  text "X" at 430.809,131.112 h1.52
  text "FR-408" at 420.483,131.103 h1.52
  text "OTHER" at 458.278,131.103 h1.52
  text "OTHER" at 464.171,127.039 h1.52
  text "64 MIL (1.626mm) +/-10%" at 428.614,126.97 h1.52
  text "THICKNESS:" at 411.689,126.861 h1.52
  text "X" at 425.358,126.861 h1.52
  text "TOLERANCE:" at 411.689,122.848 h1.52
  text "X" at 433.007,122.848 h1.52
  text "ANSI IPC-6012 TYPE 3 CLASS 2" at 437.756,122.848 h1.52
  text "OTHER +/-" at 437.755,118.885 h1.52
  text "BOW & TWIST:" at 411.689,114.898 h1.52
  text "X" at 433.007,114.898 h1.52
  text "ANSI IPC-6012 TYPE 3 CLASS 2" at 437.756,114.898 h1.52
  text "OTHER +/-" at 437.755,110.872 h1.52
  text "COPPER THICKNESS (FINISHED):" at 409.79,107.43 h1.52
  text "X" at 466.928,103.655 h1.52
  text "1.4MIL (1oz)" at 432.142,103.551 h1.52
  text "2MIL (1.4oz)" at 451.624,103.551 h1.52
  text "2.8MIL (2oz)" at 470.089,103.551 h1.52
  text "OUTER:" at 418.858,103.442 h1.52
  text "1.4MIL (1oz)" at 432.142,99.563 h1.52
  text "2.8MIL (2oz)" at 451.624,99.563 h1.52
  text "N/A" at 470.078,99.572 h1.52
  text "X" at 448.386,99.514 h1.52
  text "INNER SIGNAL:" at 411.515,99.454 h1.52
  text "DRILLING:" at 409.79,95.924 h1.52
  text "REFERENCE:" at 411.689,92.952 h1.52
  text "X" at 428.154,92.952 h1.52
  text "AS SHOWN" at 432.904,92.952 h1.52
  text "X" at 451.039,92.952 h1.52
  text "NC_DRILL FILES" at 454.519,92.952 h1.52
  text "PTH MIN COPPER THICKNESS:" at 411.689,88.939 h1.52
  text "X" at 445.985,88.939 h1.52
  text "1MIL" at 449.465,88.939 h1.52
  text "OTHER" at 462.088,88.939 h1.52
  text "BOARD FINISH:" at 409.79,84.9 h1.52
  text "SILKSCREEN:" at 413.733,81.903 h1.52
  text "X" at 437.831,81.903 h1.52
  text "TOP" at 441.032,81.903 h1.52
  text "BOTTOM" at 454.011,81.903 h1.52
  text "X" at 450.977,81.811 h1.52
  text "SILKSCREEN COLOR:" at 413.733,77.661 h1.52
  text "X" at 437.805,77.661 h1.52
  text "WHITE" at 441.032,77.661 h1.52
  text "OTHER" at 454.011,77.661 h1.52
  text "SOLDER RESIST COLOR:" at 413.733,73.343 h1.52
  text "X" at 428.153,69.3 h1.52
  text "GREEN" at 431.38,69.3 h1.52
  text "BLUE" at 446.391,69.3 h1.52
  text "OTHER" at 460.056,69.3 h1.52
  text "IMMERSION GOLD (ENIG)" at 436.739,64.511 h1.52
  text "ENEPIG" at 470.713,64.428 h1.52
  text "SURFACE FINISH:" at 409.79,64.402 h1.52
  text "X" at 431.991,64.402 h1.52
  text "IMM. TIN/SILVER OR EQUIV" at 418.16,60.415 h1.52
  text "OTHER" at 454.519,60.415 h1.52
  text "ARRAY/PANEL:" at 409.79,55.868 h1.52
  text "CUT AND TRIM PER MECH LAYER 1" at 436.739,55.759 h1.52
  text "X" at 453.695,51.94 h1.52
  text "N.C. ROUTE" at 436.739,51.906 h1.52
  text "V. SCORE" at 458.736,51.906 h1.52
  text "CERTIFICATION:" at 409.79,48.426 h1.52
  text "MATERIALS AND WORKMANSHIP FOR ALL PCBS" at 428.205,48.426 h1.52
  text "TO MEET OR EXCEED THE REQUIREMENTS OF:" at 428.205,45.937 h1.52
  text "X" at 418.718,42.469 h1.52
  text "ANSI IPC-A-600F CLASS ->" at 422.249,42.469 h1.52
  text "X" at 463.881,42.469 h1.52
  text "2" at 466.902,42.469 h1.52
  text "1" at 458.901,42.431 h1.52
  text "3" at 475.893,42.431 h1.52
  text "X" at 418.77,38.418 h1.52
  text "UL 94V-0" at 422.249,38.418 h1.52
  text "X" at 439.395,38.418 h1.52
  text "RoHS" at 442.873,38.418 h1.52
  text "OTHER" at 459.241,38.418 h1.52
  text "PER ORDER" at 469.327,38.418 h1.52
  text "VIA TENTING:" at 440.715,35.024 h1.52
  text "X" at 460.285,35.023 h1.52
  text "ADDITIONAL REQUIREMENTS:" at 409.79,34.837 h1.52
  text "YES" at 454.677,34.793 h1.52
  text "NO" at 463.943,34.66 h1.52
  text "MICROSECTION:" at 411.689,31.916 h1.52
  text "YES" at 434.695,31.916 h1.52
  text "IMPEDANCE CONTROL:" at 441.274,31.747 h1.52
  text "YES" at 466.268,31.722 h1.52
  text "X" at 479.961,31.391 h1.52
  text "NO" at 475.805,31.282 h1.52
  text "REQUIRED" at 456.577,27.95 h1.52
  text "BARE BOARD ELEC. TEST:" at 411.689,27.877 h1.52
  text "NONE" at 444.855,27.877 h1.52
  text "X" at 453.351,27.877 h1.52
  text "PER ORDER" at 471.613,27.877 h1.52
  text "MANUFACTURER'S UL:" at 411.689,23.889 h1.52
  text "RAIL" at 441.299,23.781 h1.52
  text "METAL" at 453.791,23.781 h1.52
  text "X" at 463.321,23.772 h1.52
  text "SILK" at 466.787,23.781 h1.52
  text ".Layer_Name" at 14.656,-21.806 h1.52
M11 Gerber Information:
  lines w0.254: -7.417,-23.626 160.223,-23.626 ; -7.417,-18.462 160.274,-18.462 ; -7.417,-13.297 -7.417,-28.791 94.31,-28.791 160.274,-28.791 160.274,-13.297 -7.404,-13.297 -7.404,-28.791 32.614,-28.791 ; 55.194,-28.791 55.194,-13.297 ; 87.376,-18.462 87.376,-13.297 ; 108.712,-18.462 108.712,-13.297 ; 124.511,-28.956 124.511,-23.804
  text "ALL ARTWORK VIEWED FROM TOP SIDE" at -5.804,-16.654 h1.52
  text "BOARD #:" at 57.099,-16.654 h1.52
  text ".PRJ_Number" at 70.955,-16.654 h1.52
  text "REV:" at 92.405,-16.654 h1.52
  text ".PCB_Rev" at 99.809,-16.654 h1.52
  text "SVN REV:" at 113.69,-16.654 h1.52
  text ".VersionControl_RevNumber" at 126.543,-16.654 h1.52
  text "LAYER NAME =" at -5.804,-21.806 h1.52
  text "TID #:" at 57.099,-21.819 h1.52
  text ".TID" at 70.955,-21.819 h1.52
  text "PLOT NAME =" at -5.804,-27.034 h1.52
  text ".plot_File_Name" at 14.656,-27.034 h1.52
  text "GENERATED    :" at 57.15,-27.034 h1.52
  text ".Print_Date" at 79.235,-27.034 h1.52
  text ".Print_Time" at 97.752,-27.034 h1.52
  text "TEXAS INSTRUMENTS" at 129.87,-27.034 h1.52
M12 Stackup:
  drawing of 295 lines, arcs and shapes, not listed
  text "Layer" at 381.84,215.35 h1.38
  text "Name" at 391.317,215.35 h1.38
  text "Material" at 412.75,215.35 h1.38
  text "Thickness" at 432.574,215.35 h1.38
  text "Constant" at 447.569,215.35 h1.38
  text "Board Layer Stack" at 460.725,215.35 h1.38
  text "Top Overlay" at 391.317,212.59 h1.38
  text "Top Solder" at 391.317,209.83 h1.38
  text "Solder Resist" at 412.75,209.83 h1.38
  text "0.40mil" at 432.574,209.83 h1.38
  text "3.5" at 447.569,209.83 h1.38
  text "1" at 381.84,207.07 h1.38
  text "Top Layer" at 391.317,207.07 h1.38
  text "2.80mil" at 432.574,207.07 h1.38
  text "Dielectric 2" at 391.317,204.309 h1.38
  text "FR-4 High Tq" at 412.75,204.309 h1.38
  text "12.00mil" at 432.574,204.309 h1.38
  text "4.2" at 447.569,204.309 h1.38
  text "2" at 381.84,201.549 h1.38
  text "Inner Layer1" at 391.317,201.549 h1.38
  text "2.80mil" at 432.574,201.549 h1.38
  text "Dielectric1" at 391.317,198.789 h1.38
  text "FR-4 High Tq" at 412.75,198.789 h1.38
  text "28.00mil" at 432.574,198.789 h1.38
  text "4.8" at 447.569,198.789 h1.38
  text "3" at 381.84,196.029 h1.38
  text "Inner Layer2" at 391.317,196.029 h1.38
  text "2.80mil" at 432.574,196.029 h1.38
  text "Dielectric 5" at 391.317,193.269 h1.38
  text "FR-4 High Tq" at 412.75,193.269 h1.38
  text "12.00mil" at 432.574,193.269 h1.38
  text "4.2" at 447.569,193.269 h1.38
  text "4" at 381.84,190.508 h1.38
  text "Bottom Layer" at 391.317,190.508 h1.38
  text "2.80mil" at 432.574,190.508 h1.38
  text "Bottom Solder" at 391.317,187.748 h1.38
  text "Solder Resist" at 412.75,187.748 h1.38
  text "0.40mil" at 432.574,187.748 h1.38
  text "3.5" at 447.569,187.748 h1.38
  text "Bottom Overlay" at 391.317,184.988 h1.38
  text "Total board thickness:" at 381.84,182.228 h1.38
  text "64.00mil" at 432.574,182.228 h1.38
  text ".Layer_Name" at 14.656,-21.806 h1.52
M13 Component Bodies Top:
  text ".Layer_Name" at 14.656,-21.806 h1.52
M14 Component Bodies Bottom:
  text ".Layer_Name" at 14.656,-21.806 h1.52
M15 Courtyards Top:
  text ".Layer_Name" at 14.656,-21.806 h1.52
M16 Courtyards Bottom:
  text ".Layer_Name" at 14.656,-21.806 h1.52
Drill Drawing:
  circle w0.254: c326.207,151.451 r0.7
  circle w0.254: c326.207,104.197 r0.42
  circle w0.254: c326.207,104.197 r0.7
  lines w0.254: 325.507,106.647 326.907,106.647 326.907,108.047 325.507,108.047 325.507,106.647 ; 325.507,109.797 325.507,110.147 325.857,110.497 325.507,110.847 325.507,111.197 325.857,111.197 326.207,110.847 326.557,111.197 326.907,111.197 326.907,110.847 326.557,110.497 326.907,110.147 326.907,109.797 326.557,109.797 326.207,110.147 325.857,109.797 325.507,109.797 ; 325.507,112.947 326.207,113.297 326.907,112.947 326.557,113.648 326.907,114.348 326.207,113.998 325.507,114.348 325.857,113.648 325.507,112.947 ; 325.507,129.049 325.857,129.049 325.857,128.699 326.557,128.699 326.557,129.049 326.907,129.049 326.907,129.749 326.557,129.749 326.557,130.099 325.857,130.099 325.857,129.749 325.507,129.749 325.507,129.049 ; 325.507,133.249 326.907,133.249 326.207,131.849 325.507,133.249 ; 325.507,135.349 325.857,135.349 326.207,134.999 326.557,135.349 326.907,135.349 326.557,135.699 326.907,136.049 326.557,136.049 326.207,136.4 325.857,136.049 325.507,136.049 325.857,135.699 325.507,135.349 ; 325.507,141.65 325.857,141.65 326.207,141.3 326.557,141.65 326.907,141.65 326.557,142 326.907,142.35 326.557,142.35 326.207,142.7 325.857,142.35 325.507,142.35 325.857,142 325.507,141.65 ; 325.507,155.301 326.907,155.301 326.207,153.901 325.507,155.301 ; 325.787,106.927 326.627,106.927 326.627,107.767 325.787,107.767 325.787,106.927 ; 325.787,135.489 325.997,135.489 326.207,135.279 326.417,135.489 326.627,135.489 326.417,135.699 326.627,135.909 326.417,135.909 326.207,136.119 325.997,135.909 325.787,135.909 325.997,135.699 325.787,135.489 ; 325.787,155.021 326.627,155.021 326.207,154.181 325.787,155.021
  lines w0.305: 324.238,102.552 404.981,102.552 ; 324.238,171.858 404.981,171.858 ; 332.807,99.401 332.807,175.008 ; 341.148,99.401 341.148,175.008 ; 356.165,99.401 356.165,175.008 ; 362.738,99.401 362.738,175.008 ; 372.257,99.401 372.257,175.008 ; 390.61,99.401 390.61,175.008 ; 324.238,99.401 404.981,99.401 404.981,175.008 324.238,175.008 324.238,99.401
  text "Symbol" at 326.128,172.803 h1.83
  text "Count" at 333.752,172.803 h1.83
  text "Hole Size" at 342.093,172.803 h1.83
  text "Plated" at 357.11,172.803 h1.83
  text "Hole Type" at 363.683,172.803 h1.83
  text "Drill Layer Pair" at 373.202,172.803 h1.83
  text "Hole Tolerance" at 391.555,172.803 h1.83
  text "1542" at 333.752,169.652 h1.52
  text "0.200mm (7.87mil)" at 342.093,169.652 h1.52
  text "PTH" at 357.11,169.652 h1.52
  text "Round" at 363.683,169.652 h1.52
  text "Top Layer - Bottom Layer" at 373.202,169.652 h1.52
  text "H" at 325.487,169.399 h1.4
  text "4" at 333.752,166.502 h1.52
  text "0.762mm (30.00mil)" at 342.093,166.502 h1.52
  text "PTH" at 357.11,166.502 h1.52
  text "Round" at 363.683,166.502 h1.52
  text "Top Layer - Bottom Layer" at 373.202,166.502 h1.52
  text "T" at 325.487,166.248 h1.4
  text "2" at 333.752,163.352 h1.52
  text "0.840mm (33.07mil)" at 342.093,163.352 h1.52
  text "PTH" at 357.11,163.352 h1.52
  text "Round" at 363.683,163.352 h1.52
  text "Top Layer - Bottom Layer" at 373.202,163.352 h1.52
  text "E" at 325.487,163.098 h1.4
  text "6" at 333.752,160.202 h1.52
  text "0.850mm (33.47mil)" at 342.093,160.202 h1.52
  text "PTH" at 357.11,160.202 h1.52
  text "Round" at 363.683,160.202 h1.52
  text "Top Layer - Bottom Layer" at 373.202,160.202 h1.52
  text "B" at 325.487,159.948 h1.4
  text "9" at 333.752,157.051 h1.52
  text "1.000mm (39.37mil)" at 342.093,157.051 h1.52
  text "PTH" at 357.11,157.051 h1.52
  text "Round" at 363.683,157.051 h1.52
  text "Top Layer - Bottom Layer" at 373.202,157.051 h1.52
  text "U" at 325.487,156.798 h1.4
  text "5" at 333.752,153.901 h1.52
  text "1.016mm (40.00mil)" at 342.093,153.901 h1.52
  text "PTH" at 357.11,153.901 h1.52
  text "Round" at 363.683,153.901 h1.52
  text "Top Layer - Bottom Layer" at 373.202,153.901 h1.52
  text "2" at 333.752,150.751 h1.52
  text "1.150mm (45.28mil)" at 342.093,150.751 h1.52
  text "PTH" at 357.11,150.751 h1.52
  text "Round" at 363.683,150.751 h1.52
  text "Top Layer - Bottom Layer" at 373.202,150.751 h1.52
  text "2" at 333.752,147.601 h1.52
  text "1.270mm (50.00mil)" at 342.093,147.601 h1.52
  text "NPTH" at 357.11,147.601 h1.52
  text "Round" at 363.683,147.601 h1.52
  text "Top Layer - Bottom Layer" at 373.202,147.601 h1.52
  text "F" at 325.487,147.347 h1.4
  text "16" at 333.752,144.45 h1.52
  text "1.350mm (53.15mil)" at 342.093,144.45 h1.52
  text "PTH" at 357.11,144.45 h1.52
  text "Round" at 363.683,144.45 h1.52
  text "Top Layer - Bottom Layer" at 373.202,144.45 h1.52
  text "Q" at 325.487,144.196 h1.4
  text "1" at 333.752,141.3 h1.52
  text "1.600mm (62.99mil)" at 342.093,141.3 h1.52
  text "NPTH" at 357.11,141.3 h1.52
  text "Round" at 363.683,141.3 h1.52
  text "Top Layer - Bottom Layer" at 373.202,141.3 h1.52
  text "2" at 333.752,138.15 h1.52
  text "1.600mm (63.00mil)" at 342.093,138.15 h1.52
  text "PTH" at 357.11,138.15 h1.52
  text "Round" at 363.683,138.15 h1.52
  text "Top Layer - Bottom Layer" at 373.202,138.15 h1.52
  text "N" at 325.487,137.896 h1.4
  text "32" at 333.752,134.999 h1.52
  text "1.700mm (66.93mil)" at 342.093,134.999 h1.52
  text "PTH" at 357.11,134.999 h1.52
  text "Round" at 363.683,134.999 h1.52
  text "Top Layer - Bottom Layer" at 373.202,134.999 h1.52
  text "1" at 333.752,131.849 h1.52
  text "1.800mm (70.87mil)" at 342.093,131.849 h1.52
  text "NPTH" at 357.11,131.849 h1.52
  text "Round" at 363.683,131.849 h1.52
  text "Top Layer - Bottom Layer" at 373.202,131.849 h1.52
  text "16" at 333.752,128.699 h1.52
  text "1.850mm (72.84mil)" at 342.093,128.699 h1.52
  text "PTH" at 357.11,128.699 h1.52
  text "Round" at 363.683,128.699 h1.52
  text "Top Layer - Bottom Layer" at 373.202,128.699 h1.52
  text "8" at 333.752,125.549 h1.52
  text "2.670mm (105.12mil)" at 342.093,125.549 h1.52
  text "PTH" at 357.11,125.549 h1.52
  text "Round" at 363.683,125.549 h1.52
  text "Top Layer - Bottom Layer" at 373.202,125.549 h1.52
  text "C" at 325.487,125.295 h1.4
  text "4" at 333.752,122.398 h1.52
  text "3.100mm (122.05mil)" at 342.093,122.398 h1.52
  text "PTH" at 357.11,122.398 h1.52
  text "Slot" at 363.683,122.398 h1.52
  text "Top Layer - Bottom Layer" at 373.202,122.398 h1.52
  text "O" at 325.487,122.145 h1.4
  text "6" at 333.752,119.248 h1.52
  text "3.200mm (125.98mil)" at 342.093,119.248 h1.52
  text "PTH" at 357.11,119.248 h1.52
  text "Round" at 363.683,119.248 h1.52
  text "Top Layer - Bottom Layer" at 373.202,119.248 h1.52
  text "D" at 325.487,118.994 h1.4
  text "4" at 333.752,116.098 h1.52
  text "3.200mm (125.98mil)" at 342.093,116.098 h1.52
  text "PTH" at 357.11,116.098 h1.52
  text "Slot" at 363.683,116.098 h1.52
  text "Top Layer - Bottom Layer" at 373.202,116.098 h1.52
  text "P" at 325.487,115.844 h1.4
  text "4" at 333.752,112.947 h1.52
  text "3.300mm (129.92mil)" at 342.093,112.947 h1.52
  text "NPTH" at 357.11,112.947 h1.52
  text "Round" at 363.683,112.947 h1.52
  text "Top Layer - Bottom Layer" at 373.202,112.947 h1.52
  text "3" at 333.752,109.797 h1.52
  text "3.400mm (133.86mil)" at 342.093,109.797 h1.52
  text "PTH" at 357.11,109.797 h1.52
  text "Round" at 363.683,109.797 h1.52
  text "Top Layer - Bottom Layer" at 373.202,109.797 h1.52
  text "1" at 333.752,106.647 h1.52
  text "3.600mm (141.73mil)" at 342.093,106.647 h1.52
  text "PTH" at 357.11,106.647 h1.52
  text "Round" at 363.683,106.647 h1.52
  text "Top Layer - Bottom Layer" at 373.202,106.647 h1.52
  text "4" at 333.752,103.497 h1.52
  text "5.700mm (224.41mil)" at 342.093,103.497 h1.52
  text "NPTH" at 357.11,103.497 h1.52
  text "Round" at 363.683,103.497 h1.52
  text "Top Layer - Bottom Layer" at 373.202,103.497 h1.52
  text "1674 Total" at 333.752,100.346 h1.52
  text "Slot definitions :" at 326.128,98.141 h1.52
  text "Routed Path Length" at 337.544,98.141 h1.52
  text "= Calculated from tool start centre position to tool end centre position." at 351.218,98.141 h1.52
  text "Hole Length" at 337.544,96.881 h1.52
  text "= Routed Path Length + Tool Size = Slot length as defined in the PCB layout" at 346.156,96.881 h1.52
  text "DRILL TOLARENCE:" at 325.146,87.615 h1.52
  text "FOR 7.87MIL DRILL +0/-7.87MIL" at 325.146,84.999 h1.52
  text "FOR 12MIL DRILL +0/-12MIL" at 325.146,82.382 h1.52
  text "FOR 16MIL DRILL +0/-16MIL" at 325.146,79.766 h1.52
  text "FOR PTH DRILL +/-3MIL" at 325.146,77.15 h1.52
  text "FOR NPTH DRILL +/-2MIL" at 325.146,74.534 h1.52
  text ".Layer_Name" at 14.656,-21.806 h1.52

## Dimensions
0,-10.16 to 25.4,-10.16 on M2 Board Dimensions
0,0 to 300,0 on M2 Board Dimensions
0,0 to 0,180 on M2 Board Dimensions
